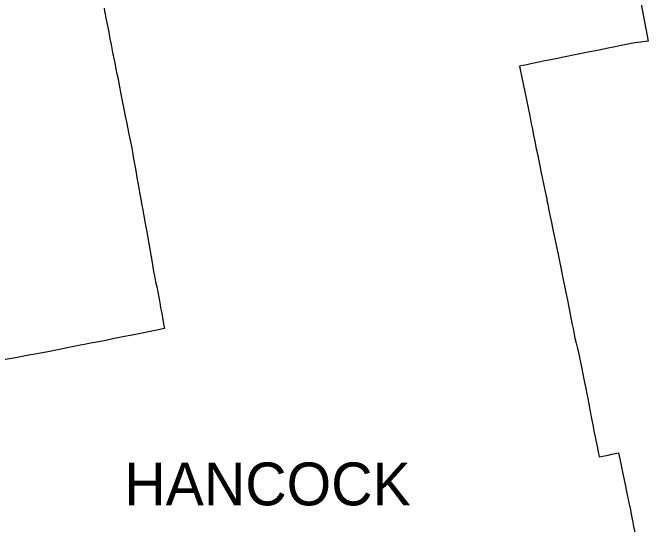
# Model space of a CAD drawing. Extents: x 1104458 to 2179854, y 15641624 to 17244911.
# Drawn here: x 1747004 to 1903646, y 16214191 to 16340321 of the extents above; entities that cross this region are included whole.
import ezdxf

# ---------------------------------------------------------------- set-up
doc = ezdxf.new("R2010")
doc.units = 0
doc.layers.add('ANNOTATION', color=7, linetype='Continuous')
doc.layers.add('CO BORDER', color=7, linetype='Continuous')

msp = doc.modelspace()

# ---------------------------------------------------------------- linework, layer by layer
at = {"layer": 'CO BORDER'}
for points in [[(1898087, 16366453), (1898247, 16365646), (1898807, 16362020), (1898939, 16361079), (1899254, 16359268), (1899373, 16358303), (1899542, 16357299), (1899689, 16356200), (1899868, 16355121), (1900031, 16354038), (1900176, 16353047), (1900322, 16351968), (1900609, 16350088), (1900641, 16349730), (1902117, 16341138), (1903646, 16333342)], [(1769523, 16341402), (1769629, 16340742), (1769809, 16339932), (1769989, 16338990), (1770423, 16336795), (1770653, 16335562), (1770980, 16333875), (1771267, 16332448), (1771635, 16330539), (1771995, 16328613), (1772143, 16327993)], [(1903646, 16333342), (1900428, 16332860), (1899427, 16332729), (1898177, 16332447), (1897002, 16332210), (1895486, 16331925), (1893786, 16331571), (1891828, 16331170), (1890686, 16330957), (1889211, 16330652), (1887587, 16330340), (1885920, 16329979), (1882745, 16329340), (1881329, 16329044), (1878188, 16328447), (1876646, 16328103), (1875063, 16327775), (1873721, 16327486), (1871877, 16327118)], [(1772143, 16327993), (1772240, 16327386), (1772617, 16325575), (1772897, 16324341), (1773192, 16322947), (1773764, 16319833), (1774428, 16316572), (1774746, 16314830), (1775033, 16313376), (1775648, 16310365), (1776222, 16307730)], [(1871877, 16327118), (1872175, 16325908), (1873224, 16320819), (1874428, 16314877), (1874805, 16312935), (1875075, 16311633), (1875386, 16310055), (1875673, 16308637), (1876017, 16306787), (1876312, 16305527), (1876640, 16303841), (1876927, 16302581), (1877353, 16300419), (1877853, 16298135), (1878247, 16296232), (1878468, 16295123), (1878607, 16294539)], [(1776222, 16307730), (1776361, 16306962), (1776614, 16305469), (1776810, 16304259), (1777022, 16303048), (1777169, 16302274), (1777243, 16301841)], [(1777243, 16301841), (1777700, 16299170), (1777888, 16298045), (1778265, 16296083), (1778510, 16294725), (1778820, 16292854), (1779033, 16291713), (1779122, 16291027), (1779368, 16289810), (1779556, 16288734), (1779940, 16286716), (1781363, 16278714), (1781657, 16277014), (1781795, 16276102), (1781853, 16275919)], [(1878607, 16294539), (1878680, 16293995), (1878877, 16293112), (1879172, 16291550), (1879492, 16290067), (1879803, 16288571), (1880139, 16286855), (1880467, 16285310), (1880753, 16283801), (1881426, 16280714), (1881745, 16279080), (1882090, 16277475), (1882450, 16275684), (1882704, 16274457), (1882998, 16272964), (1883343, 16271311), (1883711, 16269450), (1883974, 16268158), (1884219, 16266872), (1884833, 16263778), (1885104, 16262492)], [(1781853, 16275919), (1782230, 16273976), (1782492, 16272775), (1782909, 16270574), (1783155, 16269314), (1783310, 16268336), (1783449, 16267579), (1783645, 16266594), (1784259, 16263200), (1784406, 16262475)], [(1784406, 16262475), (1782131, 16261980), (1777240, 16261004), (1774132, 16260390), (1772482, 16260085), (1769124, 16259380), (1766183, 16258832), (1764725, 16258553), (1763608, 16258356), (1762883, 16258208)], [(1885104, 16262492), (1885185, 16261999), (1885562, 16260083), (1885874, 16258814), (1886178, 16257544), (1886630, 16255808), (1886811, 16254926), (1887023, 16253758), (1887278, 16252633), (1887523, 16251238), (1887859, 16249552), (1888136, 16248075), (1888489, 16246340), (1888727, 16245216), (1889406, 16241571), (1889676, 16240269), (1890028, 16238300), (1890265, 16237132), (1890495, 16236072), (1891093, 16233018), (1891314, 16231984), (1891536, 16230984), (1891535, 16230806)], [(1762883, 16258208), (1761667, 16257946), (1758575, 16257300), (1757259, 16257054), (1756184, 16256830)], [(1756184, 16256830), (1752426, 16256109), (1750993, 16255872), (1747727, 16255259), (1744702, 16254718), (1743752, 16254531), (1743028, 16254426), (1740886, 16254038), (1740020, 16253933)], [(1891535, 16230806), (1892423, 16231020), (1893723, 16231272), (1894665, 16231479), (1896340, 16231820)], [(1896340, 16231820), (1896634, 16230370), (1897329, 16227040), (1897951, 16223976), (1898302, 16222299), (1898882, 16219478), (1899226, 16217716), (1899422, 16216672), (1899838, 16214602), (1900018, 16213684), (1900492, 16211548), (1900696, 16210481), (1900942, 16209287), (1901199, 16207620), (1902234, 16202440), (1902490, 16201006)]]:
    msp.add_lwpolyline(points, dxfattribs=at)

# ---------------------------------------------------------------- texts
at = {"layer": 'ANNOTATION'}
msp.add_text('HANCOCK', height=10560.2, dxfattribs=at).set_placement((1774497, 16218857))

doc.saveas('drawing.dxf')
